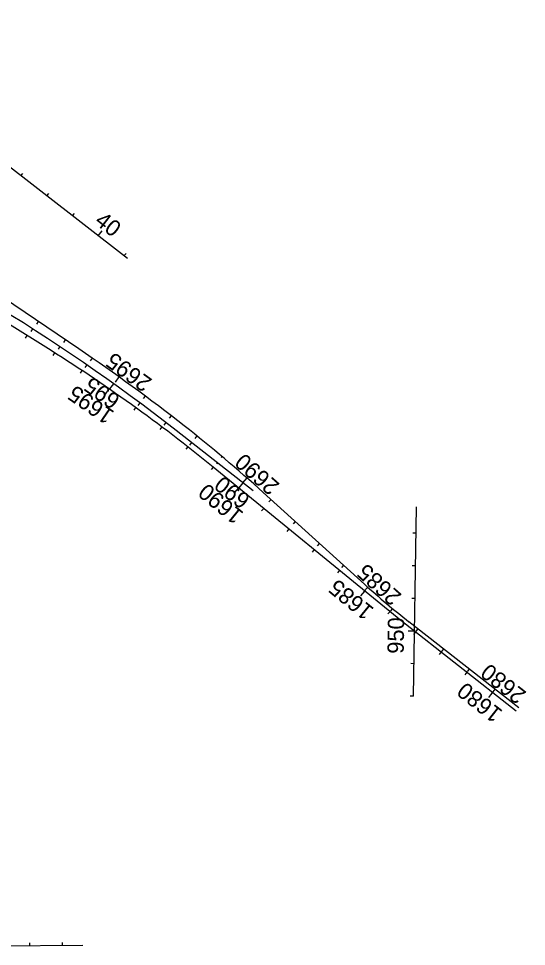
# Model space of a CAD drawing. Extents: x 448091 to 665917, y 1461380 to 1587607.
# Drawn here: x 487685 to 489243, y 1579120 to 1581965 of the extents above; entities that cross this region are included whole.
import ezdxf

# ---------------------------------------------------------------- set-up
doc = ezdxf.new("R2010")
doc.units = 0
doc.layers.add('TextShtNo', color=7, linetype='Continuous')
doc.layers.add('TextTitle', color=7, linetype='Continuous')

msp = doc.modelspace()

# ---------------------------------------------------------------- linework, layer by layer
at = {"layer": 'TextShtNo'}
for p, q in [((488018.9, 1581229.1), (487071.4, 1581965.2)), ((487870.2, 1580952.1), (487639, 1581109)), ((487768.7, 1580957.3), (487657.7, 1581026.6)), ((488404.4, 1580517.1), (488168.1, 1580701.9)), ((488857.7, 1580119.5), (488282.4, 1580589.4)), ((488746.3, 1580230.3), (488435.7, 1580511.6)), ((488896.5, 1579886.7), (488905.5, 1580467.9)), ((489211.5, 1579841.5), (488857.7, 1580119.5)), ((489219, 1579850.9), (488882.4, 1580115.4)), ((487882, 1579122.7), (487582, 1579119.5))]:
    msp.add_line(p, q, dxfattribs=at)
for centre, radius, start, end in [((484620.6, 1576164.4), 5759.7, 51.98108, 65.99774), ((485119.8, 1576716.6), 5000, 50.7637, 58.0094), ((484620.5, 1576164.4), 5786.4, 51.86675, 55.83335), ((485414.9, 1577176.2), 4500, 47.8332, 51.8668), ((490458.1, 1582120.3), 2550, 227.8332, 231.8333)]:
    msp.add_arc(centre, radius, start, end, dxfattribs=at)
at = {"layer": 'TextTitle'}
for p, q in [((487692.8, 1581482.4), (487698.9, 1581490.3)), ((487771.7, 1581421.1), (487777.9, 1581429)), ((487850.7, 1581359.7), (487856.8, 1581367.6)), ((487929.7, 1581298.4), (487941.9, 1581314.2)), ((488008.6, 1581237), (488014.8, 1581244.9)), ((487728.1, 1581013.8), (487722.7, 1581005.4)), ((487745.7, 1581036.6), (487740.1, 1581028.3)), ((487711, 1580993.4), (487705.7, 1580984.9)), ((487811.8, 1580959.1), (487806.3, 1580950.8)), ((487828.4, 1580980.4), (487822.8, 1580972.2)), ((487795.8, 1580940.3), (487790.4, 1580931.9)), ((487894.6, 1580903), (487888.9, 1580894.7)), ((487911, 1580924.1), (487905.3, 1580915.9)), ((487879.7, 1580885.9), (487874.2, 1580877.6)), ((487976.4, 1580845.4), (487964.7, 1580829.2)), ((487992.8, 1580866.5), (487981.1, 1580850.3)), ((487962.5, 1580829.9), (487951.2, 1580813.5)), ((488057.1, 1580786.4), (488051.2, 1580778.4)), ((488073.6, 1580807.6), (488067.6, 1580799.5)), ((488044.2, 1580772.2), (488038.4, 1580764.1)), ((488153.3, 1580747.2), (488147.2, 1580739.3)), ((488124.7, 1580712.9), (488118.7, 1580705)), ((488136.9, 1580726.1), (488130.8, 1580718.2)), ((488231.9, 1580685.4), (488225.6, 1580677.6)), ((488204.1, 1580652.1), (488197.9, 1580644.2)), ((488215.7, 1580664.6), (488209.6, 1580656.7)), ((488309.2, 1580622), (488306.6, 1580618.9)), ((488282.1, 1580589.6), (488275.8, 1580581.8)), ((488294.5, 1580603), (488292, 1580599.9)), ((488373.3, 1580541.4), (488361, 1580525.7)), ((488385, 1580556.8), (488371.8, 1580541.8)), ((488359.6, 1580526.3), (488346.9, 1580510.8)), ((488390.6, 1580501), (488389.3, 1580499.5)), ((488459.5, 1580490), (488452.8, 1580482.6)), ((488437, 1580463.1), (488430.7, 1580455.3)), ((488533.6, 1580422.9), (488526.9, 1580415.5)), ((488514.5, 1580399.8), (488508.2, 1580392.1)), ((488904.2, 1580386.6), (488894.2, 1580386.8)), ((488592, 1580336.6), (488585.6, 1580328.8)), ((488607.7, 1580355.8), (488601, 1580348.4)), ((488669.4, 1580273.3), (488663.1, 1580265.6)), ((488681.9, 1580288.7), (488675.1, 1580281.2)), ((488902.7, 1580286.6), (488892.7, 1580286.8)), ((488756, 1580221.6), (488742.7, 1580206.7)), ((488746.9, 1580210.1), (488734.2, 1580194.6)), ((488901.1, 1580186.6), (488891.1, 1580186.8)), ((488824.3, 1580146.8), (488818, 1580139.1)), ((488831.8, 1580156.3), (488825.4, 1580148.6)), ((488899.6, 1580086.6), (488879.6, 1580086.9)), ((488902.4, 1580084.4), (488896.3, 1580076.5)), ((488909.9, 1580093.8), (488903.7, 1580086)), ((488981.1, 1580022.6), (488974.9, 1580014.7)), ((488988.5, 1580032), (488982.3, 1580024.2)), ((488898.1, 1579986.6), (488888.1, 1579986.8)), ((489059.7, 1579960.8), (489053.5, 1579952.9)), ((489067.1, 1579970.2), (489060.9, 1579962.4)), ((489145.7, 1579908.4), (489133.4, 1579892.7)), ((488896.5, 1579886.7), (488886.5, 1579886.8)), ((489138.3, 1579899), (489125.9, 1579883.3)), ((487720.2, 1579121), (487720.1, 1579131)), ((487820.2, 1579122), (487820.1, 1579132))]:
    msp.add_line(p, q, dxfattribs=at)

# ---------------------------------------------------------------- texts
for s, rotation, p in [('40', 322.1569, (487915.6, 1581337.8)), ('2695', 144.3531, (488097.8, 1580857.3)), ('695', 144.3635, (488000.9, 1580804.1)), ('1695', 145.3514, (487982.1, 1580758.4)), ('2690', 138.6977, (488488.6, 1580537)), ('690', 141.9811, (488399.5, 1580497.1)), ('1690', 140.7637, (488378.4, 1580448.7)), ('2685', 138.1254, (488862.7, 1580197.6)), ('1685', 140.7637, (488778.1, 1580154.8)), ('950', 89.1135, (488866.2, 1580016.9)), ('2680', 141.8333, (489245.2, 1579898.3)), ('1680', 141.8333, (489172.7, 1579841))]:
    msp.add_text(s, height=50, rotation=rotation, dxfattribs=at).set_placement(p)

doc.saveas('drawing.dxf')
